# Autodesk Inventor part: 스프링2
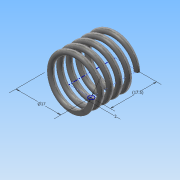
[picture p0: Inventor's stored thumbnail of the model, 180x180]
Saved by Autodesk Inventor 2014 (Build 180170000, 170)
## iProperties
Created: 2016-01
Part Number: 스프링2
Material: 강철, 탄소
Document SubType Name: Modeling
Designer: Administrator
Density: 1 g/cm^3
Appearance: 반연마
Mass: 0.819704 g
Surface Area: 16.7052 cm^2
Volume: 0.819704 cm^3
Author: Administrator
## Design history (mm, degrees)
sketch "스케치1"
  geometry: L1 (0, 0)-(8.5, 0); L2 (8.5, 0)-(8.5, 17.5); L3 (8.5, 17.5)-(0, 17.5); L4 (0, 17.5)-(0, 0); C1 r 1 at (8.5, 0)
  constraints: 8 end point, 2 parallel, 1 centre point, 1 coincident, 1 horizontal, 1 perpendicular
  dimensions: "d0" = 17.5 distance of L1.end L2.end (derived); "d1" = 2 diameter of C1; "d2" = 17 diameter of L2 L4
feature "코일1" sketch "스케치1" pitch "d3" = 10; turns "d5" = 5; dims "d4" = 17.5 (= d0), "d6" = 0, angle "d7" = 90 deg, angle "d8" = 90 deg, "d9" = 0, "d10" = 0
node "작업 평면1"
sketch "스케치2"
  geometry: L1 (7.5, 0)-(9.5, 0) reference; 1 further point
  constraints: 1 horizontal alignment
extrude "돌출1" cut sketch "스케치2" distance "d12" = 10; taper "d13" = 0 deg
node "작업 평면2"
sketch "스케치3"
  geometry: L1 (-7.5, 0)-(-9.5, 0) reference; 1 further point
  constraints: 1 horizontal alignment
extrude "돌출2" cut sketch "스케치3" distance "d15" = 10; taper "d16" = 0 deg
node "솔리드1"
node "절단 모서리 투영1"
node "절단 모서리 투영2"
other parameters: "d11" = 0, "d14" = -17.5 (= -d0)
